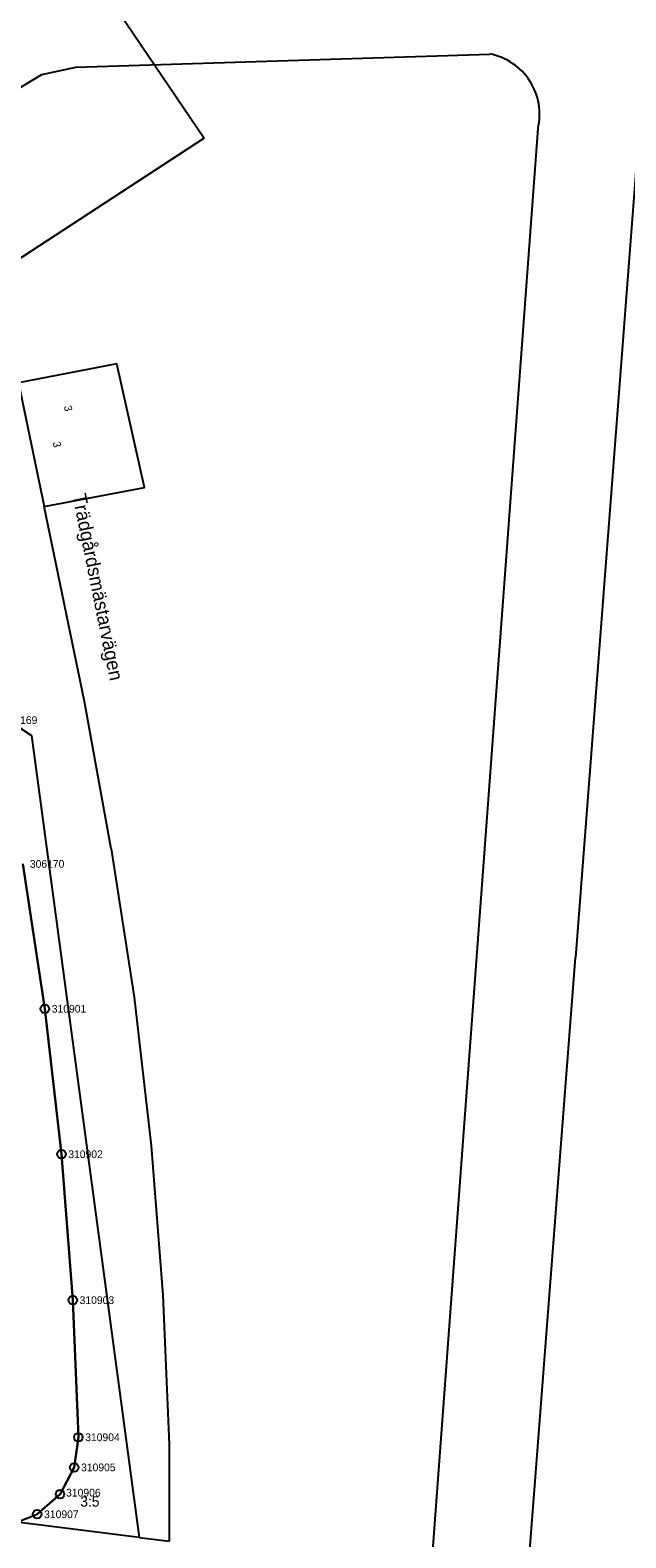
# Model space of a CAD drawing. Extents: x 141995 to 152570, y 6580184 to 6586000.
# Drawn here: x 142372.8 to 142442.1, y 6585177.1 to 6585352.4 of the extents above; entities that cross this region are included whole.
import ezdxf

# ---------------------------------------------------------------- set-up
doc = ezdxf.new("R2010")
doc.units = 0
for name, color, linetype in [('Level 10', 7, 'Continuous'), ('Level 13', 7, 'Continuous'), ('Level 20', 7, 'Continuous'), ('Level 21', 7, 'Continuous'), ('Level 43', 7, 'Continuous'), ('Level 5', 7, 'Continuous'), ('Level 51', 7, 'Continuous'), ('Level 53', 7, 'Continuous'), ('Level 54', 7, 'Continuous'), ('Level 55', 7, 'Continuous'), ('Level 6', 7, 'Continuous'), ('Level 7', 7, 'Continuous'), ('Level 8', 7, 'Continuous')]:
    doc.layers.add(name, color=color, linetype=linetype)

msp = doc.modelspace()

# ---------------------------------------------------------------- linework, layer by layer
at = {"layer": 'Level 10'}
for centre in [(142374.5, 6585238.65), (142376.42, 6585221.74), (142377.74, 6585204.77), (142378.39, 6585188.83), (142377.91, 6585185.33), (142376.26, 6585182.22), (142373.61, 6585179.88)]:
    msp.add_circle(centre, 0.5, dxfattribs=at)
at = {"layer": 'Level 13'}
for points in [[(142374.14, 6585347.28), (142378.1, 6585348.12)], [(142378.1, 6585348.12), (142426.27, 6585349.65)], [(142370.55, 6585345.1), (142374.14, 6585347.28)], [(142431.86, 6585340.99), (142417.9, 6585152.6)], [(142379.12, 6585274.36), (142374.4, 6585297.05)], [(142382.22, 6585257.25), (142379.12, 6585274.36)], [(142382.22, 6585257.26), (142384.9, 6585240)], [(142382.22, 6585257.26), (142382.22, 6585257.25)], [(142384.9, 6585240), (142386.87, 6585222.71)], [(142386.87, 6585222.71), (142388.22, 6585205.37)], [(142388.22, 6585205.37), (142388.96, 6585188)], [(142388.96, 6585188), (142388.97, 6585176.76)]]:
    msp.add_lwpolyline(points, dxfattribs=at)
msp.add_arc((142424.91, 6585342.64), 7.15, 346.6643, 79.013, dxfattribs=at)
at = {"layer": 'Level 20'}
for points in [[(142468.56, 6585644.66), (142445.03, 6585359.28), (142436.21, 6585244.62)], [(142428.51, 6585144.51), (142436.21, 6585244.62)]]:
    msp.add_lwpolyline(points, dxfattribs=at)
at = {"layer": 'Level 21'}
for points in [[(142468.56, 6585644.66), (142445.03, 6585359.28), (142436.21, 6585244.62)], [(142428.51, 6585144.51), (142436.21, 6585244.62)]]:
    msp.add_lwpolyline(points, dxfattribs=at)
at = {"layer": 'Level 5'}
for points in [[(142377.49, 6585362.87), (142393.01, 6585339.88)], [(142393.01, 6585339.88), (142359.34, 6585317.91)], [(142368.59, 6585273.25), (142372.95, 6585270.41)], [(142372.95, 6585270.41), (142385.46, 6585177.2)], [(142371.95, 6585255.49), (142374.5, 6585238.65)], [(142374.5, 6585238.65), (142376.42, 6585221.74)], [(142376.42, 6585221.74), (142377.74, 6585204.77)], [(142377.74, 6585204.77), (142378.39, 6585188.83)], [(142378.39, 6585188.83), (142377.91, 6585185.33)], [(142377.91, 6585185.33), (142376.26, 6585182.22)], [(142376.26, 6585182.22), (142373.61, 6585179.88)], [(142371.29, 6585178.98), (142373.61, 6585179.88)]]:
    msp.add_lwpolyline(points, dxfattribs=at)
at = {"layer": 'Level 6'}
msp.add_lwpolyline([(142374.4, 6585297.05), (142386.09, 6585299.25), (142382.88, 6585313.64), (142371.41, 6585311.41)], close=True, dxfattribs=at)
msp.add_lwpolyline([(142370.33, 6585178.6), (142373.61, 6585179.88), (142376.26, 6585182.22), (142377.91, 6585185.33), (142378.39, 6585188.83), (142377.74, 6585204.77), (142376.42, 6585221.74), (142374.5, 6585238.65), (142371.95, 6585255.49)], dxfattribs=at)
at = {"layer": 'Level 7'}
msp.add_lwpolyline([(142385.46, 6585177.2), (142371.29, 6585178.98)], dxfattribs=at)
at = {"layer": 'Level 8'}
msp.add_lwpolyline([(142385.46, 6585177.2), (142388.97, 6585176.76)], dxfattribs=at)

# ---------------------------------------------------------------- texts
at = {"layer": 'Level 43'}
msp.add_text('Trädgårdsmästarvägen', height=1.6, rotation=281.454, dxfattribs=at).set_placement((142377.69, 6585298.37))
at = {"layer": 'Level 51'}
msp.add_text('3:5', height=1.2, rotation=0.0522, dxfattribs=at).set_placement((142378.62, 6585180.77))
at = {"layer": 'Level 53'}
for s, rotation, p in [('306169', 0.0526, (142369.61, 6585271.76)), ('306170', 0.0526, (142372.75, 6585255.04)), ('310901', 0.0526, (142375.3, 6585238.2)), ('310902', 0.0526, (142377.22, 6585221.29)), ('310903', 0.0522, (142378.54, 6585204.32)), ('310904', 0.0522, (142379.19, 6585188.38)), ('310905', 0.0522, (142378.71, 6585184.88)), ('310906', 0.0522, (142376.97, 6585181.94)), ('310907', 0.0522, (142374.41, 6585179.43))]:
    msp.add_text(s, height=0.9, rotation=rotation, dxfattribs=at).set_placement(p)
at = {"layer": 'Level 54'}
msp.add_text('3', height=0.9, rotation=281.346, dxfattribs=at).set_placement((142376.71, 6585308.7))
at = {"layer": 'Level 55'}
msp.add_text('3', height=0.9, rotation=281.753, dxfattribs=at).set_placement((142375.4, 6585304.5))

doc.saveas('drawing.dxf')
